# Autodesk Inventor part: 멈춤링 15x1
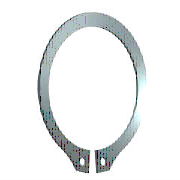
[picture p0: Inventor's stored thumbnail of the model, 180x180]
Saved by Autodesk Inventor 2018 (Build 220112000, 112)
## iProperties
Created: 2015-09
Part Number: 멈춤링 15x1
Material: 강철, 연강
Description: 리테이닝 링(C형)
Document SubType Name: Modeling
Standard: KS B 1336
Designer: mm
Standards Organization: KS
Language: ko-KR
Size Designation: 15 x 1
Categories: <MemberInstance><Categories><Category DisplayName="샤프트 부품" InternalName="7f7aeb1f-a693-4053-b835-cee3144e0d98" Mnemonic="SHFT"><Category DisplayName="써클립" Inter
Density: 1 g/cm^3
Appearance: 파란색 - 벽 페인트 - 광택
IsCustomPart: 1
Author: mduedu
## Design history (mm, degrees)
sketch "스케치1"
  geometry: L1 (-6, 0)-(6, 0) reference; L2 (0, 20.189)-(0, -80.536) reference; L3 (-48.09, 0)-(48.09, 0) reference; L4 (-0.425, -14.637)-(-0.425, -18.137); L5 (-0.425, -6.54)-(-0.425, -13.29); L6 (-2.795, 2.1)-(3.672, 2.1); L7 (0.425, -6.54)-(0.425, -13.29); L8 (0.425, -14.637)-(0.425, -18.137); C1 r 0.85 at (-1.7, -16.283); C2 r 0.85 at (1.7, -16.283); A1 r 7.15 centre (0, -7.5) between (0.425, -14.637) and (-0.425, -14.637); A2 r 9.075 centre (0, -6.975) between (4.291, -14.971) and (-4.291, -14.971); A3 r 10.646 centre (0, -7.5) between (-2.023, -17.952) and (-0.425, -18.137); A4 r 1.7 centre (-1.7, -16.283) between (-3.397, -16.376) and (-2.023, -17.952); A5 r 1.7 centre (-5.095, -16.469) between (-3.397, -16.376) and (-4.291, -14.971); A6 r 1.7 centre (5.095, -16.469) between (4.291, -14.971) and (3.397, -16.376); A7 r 1.7 centre (1.7, -16.283) between (2.023, -17.952) and (3.397, -16.376); A8 r 10.646 centre (0, -7.5) between (0.425, -18.137) and (2.023, -17.952)
  constraints: 16 point on circle, 12 end point, 10 centre point, 9 symmetric about line, 5 point on line, 4 tangent, 3 coincident, 2 horizontal, 1 perpendicular, 1 vertical, 5 other
  dimensions: "d0" = 14.3 diameter of A1 (= ND); "d1" = 3.5 distance of L4.end L4.start (= SRB2); "d6" = 0.425 distance between parallel lines of L2 L5 (= 0.25 x SD5); "d7" = 2.1 distance between parallel lines of L6 L3 (= SRB1); "d8" = 0.525 distance of A1.centre A2.centre (= 0.25 x SRB1); "d9" = 1.7 radius of A4 (= SD5); "d10" = 1.7 radius of A5 (= SD5); "d11" = 1.275 distance from line of L4 A4.centre (= 0.75 x SD5); "d12" = 1.7 diameter of C1 (= SD5); "d13" = 1.7 diameter of C2 (= SD5); "d14" = 7.5 distance from line of A1.centre L1 (= 0.5 x WD)
extrude "본체" new body sketch "스케치1" distance "d2" = 1 (= SD); taper "d3" = 0 deg
workaxis "Work Axis1"
workplane "Work Plane1"
body "Solid1"
other parameters: "WD" = 15 (= WDMIN) [user parameter; used in 1 equation term], "SD" = 1 [user parameter; used in 1 equation term], "SRB1" = 2.1 [user parameter; used in 2 equation terms], "ND" = 14.3 [user parameter; used in 1 equation term], "SRB2" = 3.5 [user parameter; used in 1 equation term], "SD5" = 1.7 [user parameter; used in 6 equation terms], "d15" = 0, "d16" = 0, "d17" = 0, "d41" = 0, "d42" = 0, "WDMIN" = 15 [user parameter; used in 1 equation term], "SD3" = 13.8 [user parameter], "WDMAX" = 16 [user parameter]
